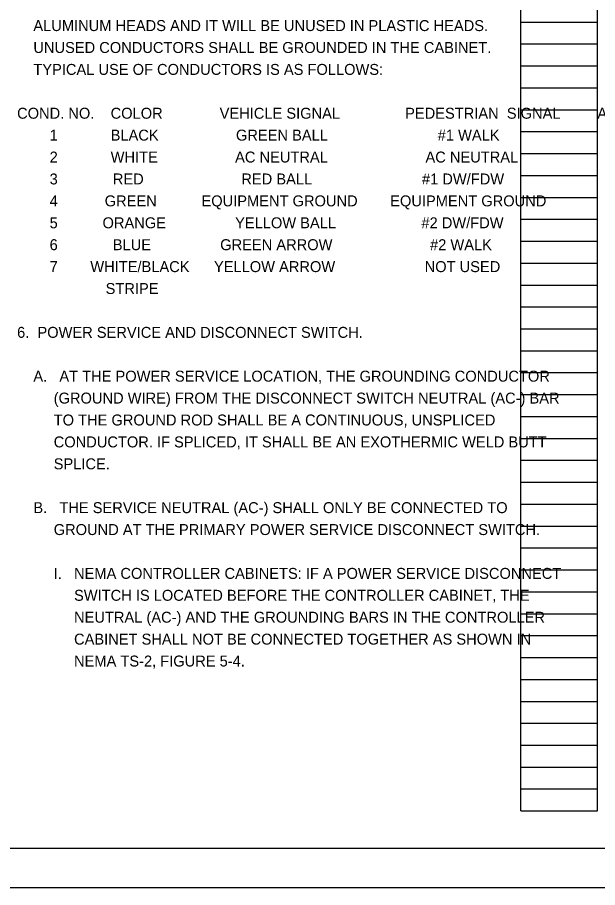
# Model space of a CAD drawing. Extents: x 0 to 34, y 0 to 22.
# Drawn here: x 17.24 to 24.66, y 0 to 11.12 of the extents above; entities that cross this region are included whole.
import ezdxf

# ---------------------------------------------------------------- set-up
doc = ezdxf.new("R2010")
doc.units = 0
for name, color, linetype in [('SH_Border', 7, 'Continuous'), ('SH_Cut_Line', 7, 'Continuous'), ('SH_Data', 7, 'Continuous'), ('SH_Text', 7, 'Continuous')]:
    doc.layers.add(name, color=color, linetype=linetype)

msp = doc.modelspace()

# ---------------------------------------------------------------- linework, layer by layer
at = {"layer": 'SH_Border'}
msp.add_lwpolyline([(1.5, 21.5), (33.5, 21.5), (33.5, 0.5), (1.5, 0.5)], close=True, dxfattribs=at)
at = {"layer": 'SH_Cut_Line'}
msp.add_lwpolyline([(0, 0), (34, 0), (34, 22), (0, 22)], close=True, dxfattribs=at)
at = {"layer": 'SH_Data'}
for p, q in [((23.68, 0.98), (23.68, 21.14)), ((24.66, 0.98), (24.66, 21.14)), ((23.68, 11.06), (24.66, 11.06)), ((23.68, 10.78), (24.66, 10.78)), ((23.68, 10.5), (24.66, 10.5)), ((23.68, 10.22), (24.66, 10.22)), ((23.68, 9.94), (24.66, 9.94)), ((23.68, 9.66), (24.66, 9.66)), ((23.68, 9.38), (24.66, 9.38)), ((23.68, 9.1), (24.66, 9.1)), ((23.68, 8.82), (24.66, 8.82)), ((23.68, 8.54), (24.66, 8.54)), ((23.68, 8.26), (24.66, 8.26)), ((23.68, 7.98), (24.66, 7.98)), ((23.68, 7.7), (24.66, 7.7)), ((23.68, 7.42), (24.66, 7.42)), ((23.68, 7.14), (24.66, 7.14)), ((23.68, 6.86), (24.66, 6.86)), ((23.68, 6.58), (24.66, 6.58)), ((23.68, 6.3), (24.66, 6.3)), ((23.68, 6.02), (24.66, 6.02)), ((23.68, 5.74), (24.66, 5.74)), ((23.68, 5.46), (24.66, 5.46)), ((23.68, 5.18), (24.66, 5.18)), ((23.68, 4.9), (24.66, 4.9)), ((23.68, 4.62), (24.66, 4.62)), ((23.68, 4.34), (24.66, 4.34)), ((23.68, 4.06), (24.66, 4.06)), ((23.68, 3.78), (24.66, 3.78)), ((23.68, 3.5), (24.66, 3.5)), ((23.68, 3.22), (24.66, 3.22)), ((23.68, 2.94), (24.66, 2.94)), ((23.68, 2.66), (24.66, 2.66)), ((23.68, 2.38), (24.66, 2.38)), ((23.68, 2.1), (24.66, 2.1)), ((23.68, 1.82), (24.66, 1.82)), ((23.68, 1.54), (24.66, 1.54)), ((23.68, 1.26), (24.66, 1.26)), ((23.68, 0.98), (24.66, 0.98))]:
    msp.add_line(p, q, dxfattribs=at)

# ---------------------------------------------------------------- texts
at = {"layer": 'SH_Text'}
for s, p in [('    ALUMINUM HEADS AND IT WILL BE UNUSED IN PLASTIC HEADS.', (17.237, 10.945)), ('    UNUSED CONDUCTORS SHALL BE GROUNDED IN THE CABINET.', (17.237, 10.665)), ('    TYPICAL USE OF CONDUCTORS IS AS FOLLOWS:', (17.237, 10.385)), ('COND. NO.    COLOR              VEHICLE SIGNAL                PEDESTRIAN  SIGNAL', (17.237, 9.825)), ('ADDITIONAL COST TO THE PROJECT. ', (24.657, 9.825)), ('        1             BLACK                   GREEN BALL                           #1 WALK', (17.237, 9.545)), ('        2             WHITE                   AC NEUTRAL                        AC NEUTRAL', (17.237, 9.265)), ('        3         ', (17.237, 8.985)), ('  RED                        RED BALL                           #1 DW/FDW', (18.357, 8.985)), ('        4         ', (17.237, 8.705)), ('GREEN           EQUIPMENT GROUND        EQUIPMENT GROUND', (18.357, 8.705)), ('        5           ORANGE                 YELLOW BALL                     #2 DW/FDW', (17.237, 8.425)), ('        6         ', (17.237, 8.145)), ('  BLUE                 GREEN ARROW                        #2 WALK', (18.357, 8.145)), ('        7        WHITE/BLACK      YELLOW ARROW                      NOT USED', (17.237, 7.865)), ('           STRIPE', (17.797, 7.585)), ('6.  POWER SERVICE AND DISCONNECT SWITCH.', (17.237, 7.025)), ('    A.   AT THE POWER SERVICE LOCATION, THE GROUNDING CONDUCTOR', (17.237, 6.465)), ('         (GROUND WIRE) FROM THE DISCONNECT SWITCH NEUTRAL (AC-) BAR', (17.237, 6.185)), ('         TO THE GROUND ROD SHALL BE A CONTINUOUS, UNSPLICED', (17.237, 5.905)), ('         CONDUCTOR. IF SPLICED, IT SHALL BE AN EXOTHERMIC WELD BUTT', (17.237, 5.625)), ('         SPLICE.', (17.237, 5.345)), ('    B.   THE SERVICE NEUTRAL (AC-) SHALL ONLY BE CONNECTED TO', (17.237, 4.785)), ('         GROUND AT THE PRIMARY POWER SERVICE DISCONNECT SWITCH.', (17.237, 4.505)), ('         I.   NEMA CONTROLLER CABINETS: IF A POWER SERVICE DISCONNECT', (17.237, 3.945)), ('              SWITCH IS LOCATED BEFORE THE CONTROLLER CABINET, THE ', (17.237, 3.665)), ('              NEUTRAL (AC-) AND THE GROUNDING BARS IN THE CONTROLLER', (17.237, 3.385)), ('              CABINET SHALL NOT BE CONNECTED TOGETHER AS SHOWN IN', (17.237, 3.105)), ('              NEMA TS-2, FIGURE 5-4.', (17.237, 2.825))]:
    msp.add_text(s, height=0.14, dxfattribs=at).set_placement(p)

doc.saveas('drawing.dxf')
